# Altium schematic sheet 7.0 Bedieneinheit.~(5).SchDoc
size A4; SheetNumber: 7; SheetTotal: 7
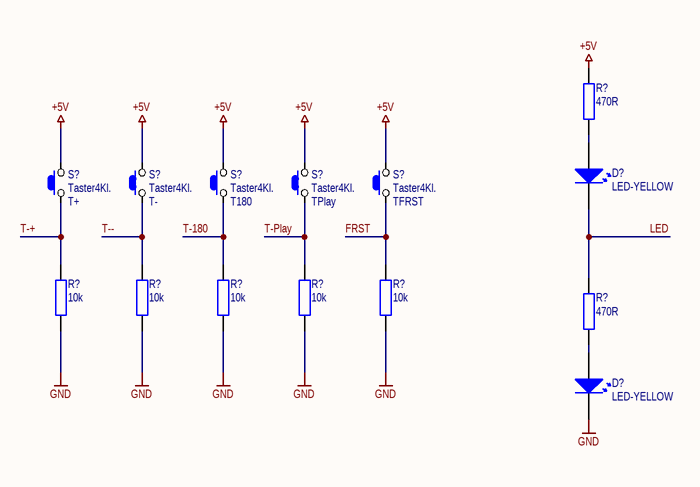
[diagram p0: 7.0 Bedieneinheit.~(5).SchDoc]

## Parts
(Parts that share a designator on the sheet are numbered #1, #2 ... from top to bottom, then left to right.)
D?#1  LED-YELLOW  [D_THT_LED-5]
D?#2  LED-YELLOW  [D_THT_LED-5]
R?#1  470R  [R_SMD_0805]
R?#2  10k  [R_SMD_0805]
R?#3  10k  [R_SMD_0805]
R?#4  10k  [R_SMD_0805]
R?#5  10k  [R_SMD_0805]
R?#6  10k  [R_SMD_0805]
R?#7  470R  [R_SMD_0805]
S?#1  Taster4Kl.  Use: T+  [S_THT_Taster4kl.]
S?#2  Taster4Kl.  Use: T-  [S_THT_Taster4kl.]
S?#3  Taster4Kl.  Use: T180  [S_THT_Taster4kl.]
S?#4  Taster4Kl.  Use: TPlay  [S_THT_Taster4kl.]
S?#5  Taster4Kl.  Use: TFRST  [S_THT_Taster4kl.]

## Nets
+5V: R?#1.2 S?#1.2 S?#2.2 S?#3.2 S?#4.2 S?#5.2
GND: D?#2.2(K) R?#2.1 R?#3.1 R?#4.1 R?#5.1 R?#6.1
FRST: R?#6.2 S?#5.1
LED: D?#1.2(K) R?#7.2
T-180: R?#4.2 S?#3.1
T-+: R?#2.2 S?#1.1
T--: R?#3.2 S?#2.1
T-Play: R?#5.2 S?#4.1
NetD?#1_1: D?#1.1(A) R?#1.1
NetD?#2_1: D?#2.1(A) R?#7.1

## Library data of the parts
D?#1 D?#2 = D_THT_LED: Diode THT LED; Spannung For.: 1,8V-3,6V
R?#1-R?#7 = R_SMD_Widerstand: Widerstand SMD
S?#1-S?#5 = S_THT_Taster: Taster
